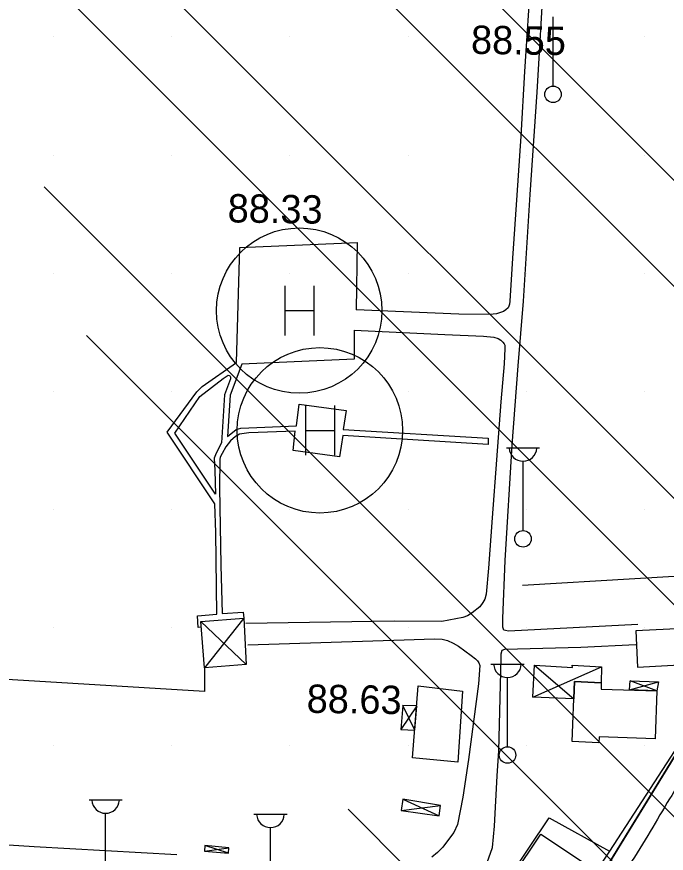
# Model space of a CAD drawing. Extents: x 417995 to 421451, y 4454518 to 4458015.
# Drawn here: x 420306.6 to 420444, y 4455397.6 to 4455574.7 of the extents above; entities that cross this region are included whole.
import ezdxf

# ---------------------------------------------------------------- set-up
doc = ezdxf.new("R2010")
doc.units = 0
for name, color, linetype in [('ADAKENARI', 7, 'Continuous'), ('B_Betonzemin', 7, 'Continuous'), ('B_Mesken', 7, 'Continuous'), ('B_Sundurma', 7, 'Continuous'), ('Egri_1m', 7, 'Continuous'), ('PL_KAMU_HİZMET_ALANI', 7, 'Continuous'), ('S_Cad_Sok_Lambasi', 7, 'Continuous'), ('S_Helikopter_Pisti', 7, 'Continuous'), ('Sinir_itirazli_Mulkiyet', 7, 'Continuous'), ('Sinir_Tel_bir_taraf', 7, 'Continuous'), ('SN_TR_SIVILASMA', 7, 'Continuous'), ('TRFAT_KHA', 7, 'Continuous'), ('Y_Kot_Noktasi', 7, 'Continuous'), ('Y_Yol_Kotu', 7, 'Continuous'), ('Yol_Sose', 7, 'Continuous')]:
    doc.layers.add(name, color=color, linetype=linetype)

msp = doc.modelspace()

# ---------------------------------------------------------------- linework, layer by layer
at = {"layer": 'ADAKENARI'}
msp.add_line((420457.92, 4455437.99), (420419.68, 4455375.72), dxfattribs=at)
at = {"layer": 'B_Betonzemin'}
for points in [[(420345.58, 4455445.47), (420344.95, 4455445.41), (420344.83, 4455447.9), (420348.9, 4455448.21), (420348.71, 4455465.53), (420348.46, 4455471.59), (420338.37, 4455486.73), (420344.64, 4455495.26), (420345.81, 4455496.44), (420353.07, 4455501.49), (420353.77, 4455525.8), (420378.6, 4455526.88), (420378.38, 4455512.66)], [(420377.98, 4455508.33), (420377.99, 4455502.19), (420354.16, 4455501.11), (420351.74, 4455494.58), (420351.15, 4455485.83), (420353.01, 4455487.31), (420353.98, 4455487.62), (420365.78, 4455488.09), (420366.35, 4455492.68), (420376.28, 4455491.32), (420375.61, 4455487.28), (420406.34, 4455485.49), (420406.32, 4455484.12), (420375.53, 4455486.01), (420374.83, 4455481.54), (420365.06, 4455482.87), (420365.48, 4455486.97), (420355.69, 4455486.61), (420353.67, 4455486.3), (420352.82, 4455485.83), (420351.78, 4455484.92), (420350.82, 4455483.64), (420350, 4455482.24), (420349.62, 4455481.48), (420349.56, 4455480.94), (420349.47, 4455475.01), (420349.74, 4455458.58), (420350.02, 4455448.38), (420354.49, 4455448.68), (420354.61, 4455447.4)], [(420348.49, 4455478.66), (420348.6, 4455473.6), (420340.03, 4455486.55), (420345.33, 4455494.3), (420350.25, 4455498.13), (420351.29, 4455498.78), (420351.51, 4455498.76), (420351.64, 4455498.69), (420351.75, 4455498.57), (420351.8, 4455498.43), (420351.76, 4455498.04), (420350.55, 4455494.66), (420349.89, 4455484.46), (420348.76, 4455482.27), (420348.33, 4455481.25)], [(420348.33, 4455481.25), (420348.49, 4455478.66)]]:
    msp.add_lwpolyline(points, dxfattribs=at)
at = {"layer": 'B_Mesken'}
for points in [[(420437.53, 4455444.72), (420437.88, 4455437.03), (420458.26, 4455438.13), (420457, 4455450.11), (420450.21, 4455449.66), (420450.55, 4455445.35)], [(420399.89, 4455416.93), (420390.29, 4455417.84), (420391.53, 4455433.07), (420400.9, 4455431.96)], [(420424.57, 4455434), (420430.24, 4455433.71), (420430.22, 4455432.38), (420442.02, 4455431.98), (420441.64, 4455421.83), (420429.81, 4455422.25), (420429.76, 4455421.02), (420424.09, 4455421.28)], [(420411.44, 4455392.68), (420417.44, 4455401.69), (420426.46, 4455395.66), (420422.93, 4455390.49), (420424.43, 4455389.46), (420419.56, 4455381.9), (420417.41, 4455383.46), (420416.78, 4455382.55), (420409.08, 4455387.85), (420412.14, 4455392.2)]]:
    msp.add_lwpolyline(points, close=True, dxfattribs=at)
at = {"layer": 'B_Sundurma'}
for p, q in [((420355.12, 4455437.6), (420345.48, 4455446.65)), ((420354.61, 4455447.4), (420346.3, 4455436.87)), ((420415.76, 4455430.64), (420430.26, 4455437.1)), ((420416.12, 4455437.46), (420424.43, 4455430.3)), ((420436.21, 4455432.18), (420442.37, 4455433.89)), ((420442.02, 4455431.98), (420436.33, 4455434.11)), ((420390.77, 4455423.65), (420388.24, 4455428.91)), ((420391.19, 4455428.8), (420387.86, 4455423.82)), ((420387.88, 4455406.65), (420396.24, 4455407.75)), ((420388.28, 4455409.05), (420395.95, 4455405.57)), ((420346.28, 4455398.07), (420351.46, 4455398.81)), ((420351.35, 4455397.65), (420346.36, 4455399.28))]:
    msp.add_line(p, q, dxfattribs=at)
for points in [[(420354.61, 4455447.4), (420355.12, 4455437.6), (420346.3, 4455436.87), (420345.48, 4455446.65)], [(420424.43, 4455430.3), (420415.76, 4455430.64), (420416.12, 4455437.46), (420424.14, 4455436.95), (420424.12, 4455437.44), (420430.26, 4455437.1), (420430.24, 4455433.71), (420424.57, 4455434)], [(420442.02, 4455431.98), (420436.21, 4455432.18), (420436.33, 4455434.11), (420442.37, 4455433.89)], [(420390.77, 4455423.65), (420391.19, 4455428.8), (420388.24, 4455428.91), (420387.86, 4455423.82)], [(420388.28, 4455409.05), (420387.88, 4455406.65), (420395.95, 4455405.57), (420396.24, 4455407.75)], [(420346.28, 4455398.07), (420351.35, 4455397.65), (420351.46, 4455398.81), (420346.36, 4455399.28)]]:
    msp.add_lwpolyline(points, close=True, dxfattribs=at)
at = {"layer": 'Egri_1m'}
msp.add_spline([(420529.85, 4455539.01), (420528.37, 4455541.15), (420525.37, 4455543.41), (420522.12, 4455545.14), (420517.31, 4455547.53), (420512.93, 4455549.77), (420507.74, 4455553), (420504.04, 4455556.97), (420501.71, 4455559.26), (420498.31, 4455560.13), (420494.4, 4455558.86), (420491.8, 4455555.23), (420489.81, 4455549.89), (420488.01, 4455543.31), (420486.3, 4455533.92), (420484.83, 4455524.93), (420483.43, 4455515.66), (420482.28, 4455509.25), (420478.56, 4455494.59), (420473.12, 4455478.85), (420470.3, 4455469.61), (420468.17, 4455461.51), (420464.99, 4455450.35), (420461.81, 4455442.38), (420459.61, 4455437.74), (420457.7, 4455433.68), (420455.56, 4455429), (420452.62, 4455423.3), (420447.9, 4455414.49), (420444.22, 4455408.35), (420440.1, 4455401.39), (420435.45, 4455394.09), (420431.14, 4455388.28), (420427.09, 4455383.15), (420423.82, 4455378.74), (420420.36, 4455373.24), (420416.32, 4455366.16), (420412.58, 4455360.61), (420410.09, 4455356.63), (420404.24, 4455347.7), (420401.03, 4455341.39), (420398.32, 4455335.98), (420396, 4455331.86), (420393.85, 4455326.9), (420393.25, 4455322.74), (420393.74, 4455318.55), (420395.21, 4455315.66), (420397.79, 4455313.28), (420401.83, 4455310.75), (420404.8, 4455309.18)], degree=3, dxfattribs=at)
at = {"layer": 'PL_KAMU_HİZMET_ALANI'}
msp.add_lwpolyline([(420584.65, 4456067.45), (420582.08, 4456000.28), (420578.04, 4455894.75), (420575.94, 4455889.49), (420550.56, 4455835.6), (420525.22, 4455781.05), (420516.32, 4455752.85), (420511.56, 4455731.89), (420506.44, 4455709.38), (420499.28, 4455692.79), (420495.57, 4455677.66), (420488.85, 4455650.29), (420482.66, 4455589.65), (420479.31, 4455554.16), (420467.35, 4455501.65), (420461.1, 4455474.22), (420459.55, 4455467.41), (420458.85, 4455454.77), (420457.92, 4455437.99), (420419.68, 4455375.72)], dxfattribs=at)
msp.add_lwpolyline([(420516.5, 4455415.06), (420469.18, 4455321.33), (420459.6, 4455298.36), (420456.9, 4455291.9), (420388.66, 4455320.38), (420397.16, 4455340.76), (420397.16, 4455340.76), (420419.68, 4455375.72), (420457.92, 4455437.99), (420458.85, 4455454.77), (420525.87, 4455433.64)], close=True, dxfattribs=at)
at = {"layer": 'S_Cad_Sok_Lambasi'}
for p, q in [((420420.04, 4455559.99), (420420.04, 4455574.66)), ((420410.19, 4455483.42), (420417.19, 4455483.42)), ((420413.69, 4455465.92), (420413.69, 4455480.6)), ((420406.9, 4455437.67), (420413.9, 4455437.67)), ((420410.4, 4455420.17), (420410.4, 4455434.85)), ((420321.85, 4455408.92), (420328.85, 4455408.92)), ((420325.35, 4455391.42), (420325.35, 4455406.09)), ((420356.75, 4455405.88), (420363.75, 4455405.88)), ((420360.25, 4455388.38), (420360.25, 4455403.06))]:
    msp.add_line(p, q, dxfattribs=at)
for centre in [(420420.04, 4455558.24), (420413.69, 4455464.17), (420410.4, 4455418.42)]:
    msp.add_circle(centre, 1.75, dxfattribs=at)
for centre in [(420413.69, 4455483.52), (420410.4, 4455437.78), (420325.35, 4455409.02), (420360.25, 4455405.99)]:
    msp.add_arc(centre, 2.93, 183.298, 356.9072, dxfattribs=at)
at = {"layer": 'S_Helikopter_Pisti'}
for p, q in [((420363.28, 4455517.73), (420363.28, 4455507.23)), ((420369.4, 4455517.73), (420369.4, 4455507.23)), ((420363.28, 4455512.48), (420369.4, 4455512.48)), ((420367.64, 4455492.38), (420367.64, 4455481.88)), ((420373.77, 4455492.38), (420373.77, 4455481.88)), ((420367.64, 4455487.13), (420373.77, 4455487.13))]:
    msp.add_line(p, q, dxfattribs=at)
for centre in [(420366.33, 4455512.47), (420370.7, 4455487.13)]:
    msp.add_circle(centre, 17.5, dxfattribs=at)
at = {"layer": 'Sinir_itirazli_Mulkiyet'}
msp.add_lwpolyline([(420346.3, 4455436.87), (420346.26, 4455431.88), (420264.96, 4455436.81)], dxfattribs=at)
at = {"layer": 'Sinir_Tel_bir_taraf'}
for points in [[(420496.53, 4455798.91), (420497.02, 4455772.86), (420496.93, 4455765.3), (420534.35, 4455759.88), (420526.25, 4455731.65), (420521.6, 4455716.39), (420520.13, 4455706.43), (420500.47, 4455707.08), (420494.39, 4455667.48), (420489.59, 4455619.74), (420484.53, 4455562.59), (420474.78, 4455512.98), (420469.53, 4455490.99), (420464.58, 4455470.23), (420461.13, 4455457.12), (420413.58, 4455454.28)], [(420457.32, 4455438.08), (420446.56, 4455420.57), (420431.96, 4455398.09)], [(420398.42, 4455373.78), (420406.29, 4455385.87), (420419.21, 4455405.14), (420431.96, 4455398.09), (420416.11, 4455374.06), (420406.29, 4455359.39), (420401.9, 4455353.2), (420385.38, 4455332.37), (420377.52, 4455322.43)]]:
    msp.add_lwpolyline(points, dxfattribs=at)
at = {"layer": 'SN_TR_SIVILASMA'}
for p, q in [((420983.3, 4455002.39), (420204.76, 4455780.94)), ((420960.61, 4455002.63), (420211.17, 4455752.07)), ((420915.23, 4455003.11), (420224, 4455694.34)), ((420892.54, 4455003.35), (420230.42, 4455665.47)), ((420847.16, 4455003.83), (420312.35, 4455538.64)), ((420824.47, 4455004.07), (420321.33, 4455507.21)), ((420779.09, 4455004.55), (420376.67, 4455406.97))]:
    msp.add_line(p, q, dxfattribs=at)
at = {"layer": 'TRFAT_KHA'}
for p, q in [((420314.37, 4455570.38), (420314.37, 4455570.38)), ((420339.37, 4455570.38), (420339.37, 4455570.38)), ((420364.37, 4455570.38), (420364.37, 4455570.38)), ((420389.37, 4455570.38), (420389.37, 4455570.38)), ((420414.37, 4455570.38), (420414.37, 4455570.38)), ((420439.37, 4455570.38), (420439.37, 4455570.38)), ((420314.37, 4455545.38), (420314.37, 4455545.38)), ((420339.37, 4455545.38), (420339.37, 4455545.38)), ((420364.37, 4455545.38), (420364.37, 4455545.38)), ((420389.37, 4455545.38), (420389.37, 4455545.38)), ((420414.37, 4455545.38), (420414.37, 4455545.38)), ((420439.37, 4455545.38), (420439.37, 4455545.38)), ((420314.37, 4455520.38), (420314.37, 4455520.38)), ((420339.37, 4455520.38), (420339.37, 4455520.38)), ((420364.37, 4455520.38), (420364.37, 4455520.38)), ((420389.37, 4455520.38), (420389.37, 4455520.38)), ((420414.37, 4455520.38), (420414.37, 4455520.38)), ((420439.37, 4455520.38), (420439.37, 4455520.38)), ((420314.37, 4455495.38), (420314.37, 4455495.38)), ((420339.37, 4455495.38), (420339.37, 4455495.38)), ((420364.37, 4455495.38), (420364.37, 4455495.38)), ((420389.37, 4455495.38), (420389.37, 4455495.38)), ((420414.37, 4455495.38), (420414.37, 4455495.38)), ((420439.37, 4455495.38), (420439.37, 4455495.38)), ((420314.37, 4455470.38), (420314.37, 4455470.38)), ((420339.37, 4455470.38), (420339.37, 4455470.38)), ((420364.37, 4455470.38), (420364.37, 4455470.38)), ((420389.37, 4455470.38), (420389.37, 4455470.38)), ((420414.37, 4455470.38), (420414.37, 4455470.38)), ((420439.37, 4455470.38), (420439.37, 4455470.38)), ((420314.37, 4455445.38), (420314.37, 4455445.38)), ((420339.37, 4455445.38), (420339.37, 4455445.38)), ((420364.37, 4455445.38), (420364.37, 4455445.38)), ((420389.37, 4455445.38), (420389.37, 4455445.38)), ((420414.37, 4455445.38), (420414.37, 4455445.38)), ((420439.37, 4455445.38), (420439.37, 4455445.38)), ((420314.37, 4455420.38), (420314.37, 4455420.38)), ((420339.37, 4455420.38), (420339.37, 4455420.38)), ((420364.37, 4455420.38), (420364.37, 4455420.38)), ((420389.37, 4455420.38), (420389.37, 4455420.38)), ((420414.37, 4455420.38), (420414.37, 4455420.38)), ((420439.37, 4455420.38), (420439.37, 4455420.38))]:
    msp.add_line(p, q, dxfattribs=at)
at = {"layer": 'Yol_Sose'}
for points in [[(420437.97, 4455446.07), (420410.6, 4455444.63), (420409.97, 4455444.74), (420409.62, 4455444.87), (420409.4, 4455445.47), (420409.41, 4455447.3), (420409.92, 4455459.59), (420411.41, 4455483.96), (420412.63, 4455500.81), (420413.81, 4455514.48), (420415.2, 4455537.05), (420416.67, 4455558.68), (420418.13, 4455584.03), (420420.01, 4455610.49), (420421.1, 4455633.01), (420422.86, 4455659.59), (420424.69, 4455682.83), (420425.94, 4455704.32), (420426.71, 4455724.41), (420428.19, 4455745.75), (420430.32, 4455767.98), (420432.23, 4455785.83), (420433.16, 4455801.93)], [(420415.36, 4455583.58), (420413.99, 4455563.05), (420413.19, 4455549.4), (420412.37, 4455536.9), (420411.44, 4455523.54), (420410.88, 4455514.49), (420410.8, 4455513.84), (420410.7, 4455513.43), (420410.53, 4455513.07), (420410.08, 4455512.66), (420409.54, 4455512.3), (420408.9, 4455512.05), (420408.11, 4455511.79), (420407.39, 4455511.7), (420406.73, 4455511.65), (420400.13, 4455511.75), (420378.38, 4455512.66)], [(420377.98, 4455508.33), (420397.15, 4455507.43), (420405.33, 4455507.06), (420407.53, 4455506.88), (420408.4, 4455506.54), (420409, 4455506.23), (420409.45, 4455505.82), (420409.7, 4455505.44), (420409.81, 4455505.13), (420409.86, 4455504.47), (420409.67, 4455501.2), (420409, 4455493.14), (420407.18, 4455468.63), (420406.35, 4455457.99), (420405.87, 4455452.49), (420405.58, 4455451.38), (420405.21, 4455450.7), (420404.53, 4455449.81), (420402.94, 4455448.49), (420401.92, 4455447.9), (420400.98, 4455447.51), (420396.54, 4455446.69), (420386.39, 4455446.75), (420355.01, 4455446.28)], [(420355.48, 4455441.76), (420388.53, 4455442.81), (420394.86, 4455443.01), (420396.61, 4455442.93), (420397.72, 4455442.65), (420398.92, 4455442.08), (420400.04, 4455441.45), (420402.7, 4455439.46), (420403.6, 4455438.76), (420404.08, 4455438.32), (420404.32, 4455437.93), (420404.53, 4455437.34), (420404.29, 4455433.47), (420402.13, 4455417.46), (420400.95, 4455409.47), (420399.79, 4455403.73), (420399.03, 4455402), (420397.95, 4455400.51), (420396.71, 4455398.92), (420395.6, 4455397.8), (420394.36, 4455396.77)], [(420396.31, 4455372.25), (420404.28, 4455390.53), (420407.22, 4455398.82), (420407.65, 4455403.38), (420408.2, 4455413.98), (420408.54, 4455419.3), (420409.05, 4455438.85), (420409.05, 4455439.83), (420409.27, 4455440.6), (420409.87, 4455440.84), (420425.92, 4455441.27), (420437.53, 4455441.79)], [(420340.43, 4455397.27), (420310.21, 4455399.02), (420275.32, 4455401.22)]]:
    msp.add_lwpolyline(points, dxfattribs=at)

# ---------------------------------------------------------------- texts
at = {"layer": 'Y_Kot_Noktasi'}
for s, p in [('88.33', (420351.16, 4455531.15)), ('88.63', (420367.88, 4455427.36))]:
    msp.add_text(s, height=6, rotation=359.1542, dxfattribs=at).set_placement(p)
at = {"layer": 'Y_Yol_Kotu'}
msp.add_text('88.55', height=6, rotation=359.1542, dxfattribs=at).set_placement((420402.65, 4455566.82))

doc.saveas('drawing.dxf')
